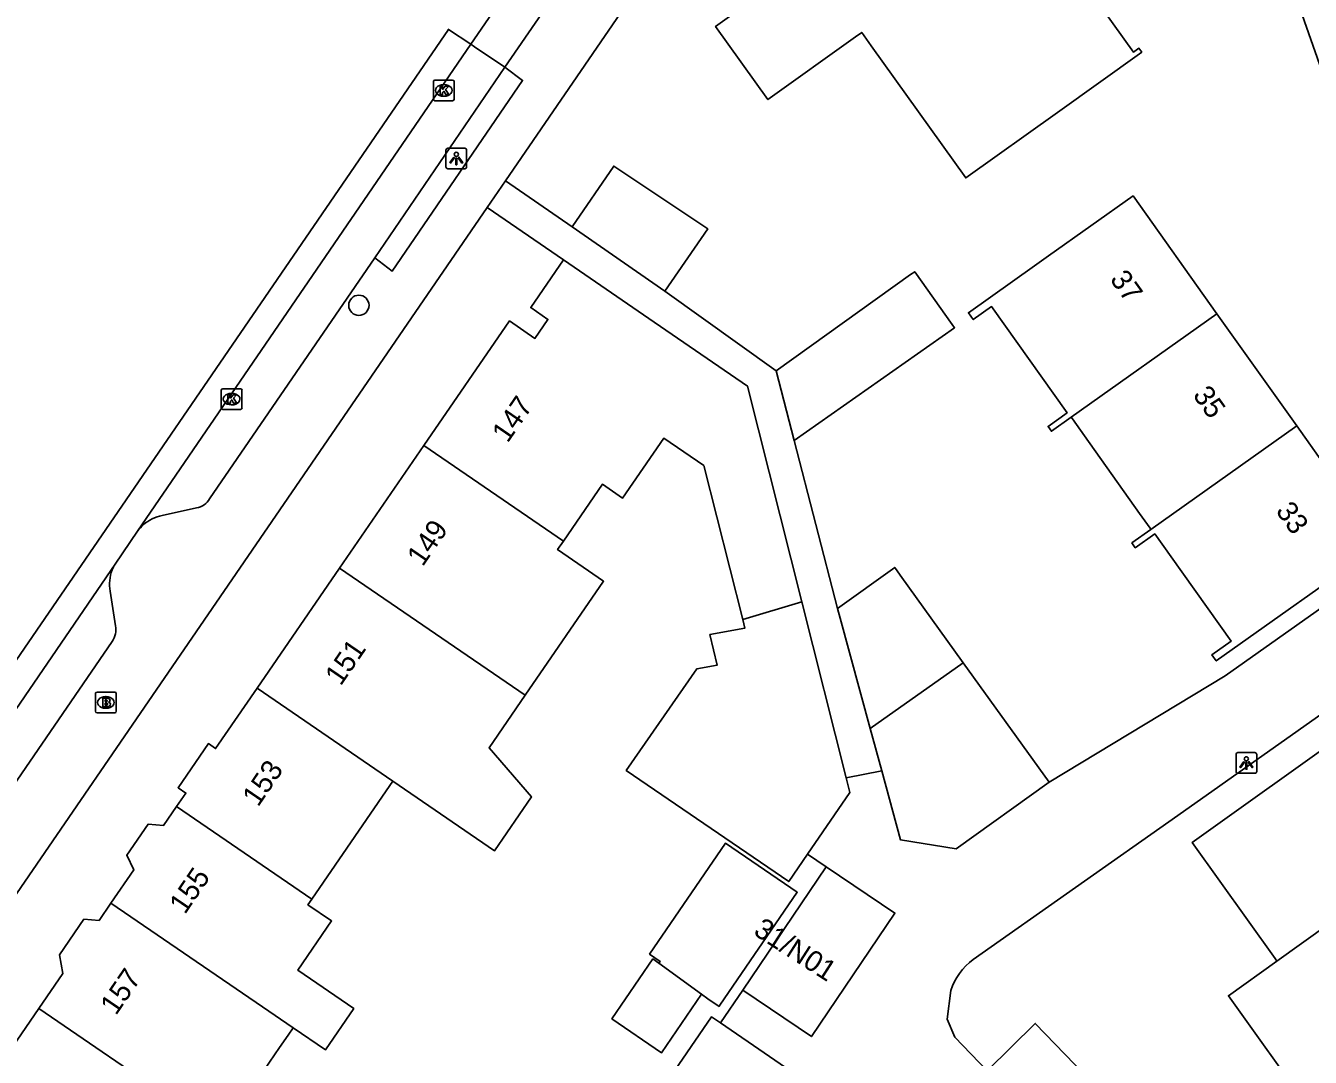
# Model space of a CAD drawing. Extents: x 160026 to 161302, y 384757 to 385701.
# Drawn here: x 160214.8 to 160276.8, y 385572.5 to 385622.3 of the extents above; entities that cross this region are included whole.
import ezdxf

# ---------------------------------------------------------------- set-up
doc = ezdxf.new("R2010")
doc.units = 0
for name, color, linetype in [('IMGEO_Boom', 7, 'Continuous'), ('IMGEO_Brandkraan', 7, 'Continuous'), ('IMGEO_Kolk', 7, 'Continuous'), ('IMGEO_Lichtpunt', 7, 'Continuous'), ('IMGEO_Muur', 7, 'Continuous'), ('IMGEO_Pand', 7, 'Continuous'), ('IMGEO_Pand_nummerreeks', 7, 'Continuous'), ('IMGEO_Parkeervlak_open', 7, 'Continuous'), ('IMGEO_Rijbaan_lokaal_gesloten', 7, 'Continuous'), ('IMGEO_Rijbaan_lokaal_open', 7, 'Continuous'), ('IMGEO_Voetpad_open', 7, 'Continuous')]:
    doc.layers.add(name, color=color, linetype=linetype)

msp = doc.modelspace()

# ---------------------------------------------------------------- linework, layer by layer
at = {"layer": 'IMGEO_Boom'}
msp.add_circle((160230.925, 385608.815), 0.489, dxfattribs=at)
at = {"layer": 'IMGEO_Brandkraan'}
for p, q in [((160218.217, 385589.217), (160218.217, 385590.069)), ((160218.292, 385590.143), (160219.144, 385590.143)), ((160219.218, 385590.069), (160219.218, 385589.217)), ((160218.728, 385589.363), (160218.703, 385589.363)), ((160218.705, 385589.923), (160218.73, 385589.923)), ((160219.144, 385589.143), (160218.292, 385589.143))]:
    msp.add_line(p, q, dxfattribs=at)
for points in [[(160218.217, 385589.217), (160218.217, 385590.069)], [(160218.292, 385590.143), (160219.144, 385590.143)], [(160219.218, 385590.069), (160219.218, 385589.217)], [(160218.565, 385589.843), (160218.565, 385589.443), (160218.778, 385589.443)], [(160218.796, 385589.843), (160218.565, 385589.843)], [(160218.744, 385589.762), (160218.69, 385589.762), (160218.69, 385589.686)], [(160218.69, 385589.686), (160218.743, 385589.686)], [(160218.752, 385589.61), (160218.69, 385589.61), (160218.69, 385589.529)], [(160218.69, 385589.529), (160218.752, 385589.529)], [(160219.144, 385589.143), (160218.292, 385589.143)]]:
    msp.add_lwpolyline(points, dxfattribs=at)
for centre, radius, start, end in [((160218.294, 385590.067), 0.0765, 91.55205, 178.44795), ((160218.294, 385590.067), 0.0765, 91.55205, 178.44795), ((160219.142, 385590.067), 0.0765, 1.55205, 88.44795), ((160219.142, 385590.067), 0.0765, 1.55205, 88.44795), ((160218.745, 385589.724), 0.0379, 267.82845, 90.93552), ((160218.753, 385589.569), 0.0404, 269.87594, 90.50774), ((160218.784, 385589.694), 0.251, 268.66757, 293.53466), ((160218.8, 385589.698), 0.145, 59.4692, 91.53667), ((160218.825, 385589.745), 0.0922, 285.51372, 58.15012), ((160218.83, 385589.553), 0.105, 301.31148, 78.98903), ((160218.294, 385589.219), 0.0765, 181.55205, 268.44795), ((160218.294, 385589.219), 0.0765, 181.55205, 268.44795), ((160219.142, 385589.219), 0.0765, 271.55205, 358.44795), ((160219.142, 385589.219), 0.0765, 271.55205, 358.44795)]:
    msp.add_arc(centre, radius, start, end, dxfattribs=at)
for centre, major_axis, ratio, start_param, end_param in [((160218.704, 385589.643), (-0.387, 0.002), 0.722429, 4.712389, 7.853982), ((160218.729, 385589.643), (-0.39, 0.002), 0.717154, 1.570796, 4.712389)]:
    msp.add_ellipse(centre, major_axis=major_axis, ratio=ratio, start_param=start_param, end_param=end_param, dxfattribs=at)
at = {"layer": 'IMGEO_Kolk'}
for p, q in [((160234.593, 385619.69), (160235.445, 385619.69)), ((160234.518, 385618.764), (160234.518, 385619.616)), ((160235.006, 385619.47), (160235.031, 385619.47)), ((160235.519, 385619.616), (160235.519, 385618.764)), ((160235.445, 385618.69), (160234.593, 385618.69)), ((160235.029, 385618.91), (160235.004, 385618.91)), ((160224.283, 385603.863), (160224.283, 385604.715)), ((160224.358, 385604.789), (160225.21, 385604.789)), ((160224.771, 385604.569), (160224.796, 385604.569)), ((160225.284, 385604.715), (160225.284, 385603.863)), ((160225.21, 385603.789), (160224.358, 385603.789)), ((160224.794, 385604.009), (160224.769, 385604.009))]:
    msp.add_line(p, q, dxfattribs=at)
for points in [[(160234.593, 385619.69), (160235.445, 385619.69)], [(160234.518, 385618.764), (160234.518, 385619.616)], [(160234.839, 385619.39), (160234.962, 385619.39), (160234.962, 385619.239), (160235.092, 385619.39), (160235.256, 385619.39), (160235.11, 385619.239), (160235.263, 385618.99), (160235.111, 385618.99), (160235.026, 385619.154), (160234.962, 385619.087), (160234.962, 385618.99), (160234.839, 385618.99), (160234.839, 385619.39)], [(160235.519, 385619.616), (160235.519, 385618.764)], [(160235.445, 385618.69), (160234.593, 385618.69)], [(160224.283, 385603.863), (160224.283, 385604.715)], [(160224.358, 385604.789), (160225.21, 385604.789)], [(160224.604, 385604.489), (160224.727, 385604.489), (160224.727, 385604.338), (160224.857, 385604.489), (160225.021, 385604.489), (160224.875, 385604.338), (160225.028, 385604.089), (160224.876, 385604.089), (160224.791, 385604.253), (160224.727, 385604.186), (160224.727, 385604.089), (160224.604, 385604.089), (160224.604, 385604.489)], [(160225.284, 385604.715), (160225.284, 385603.863)], [(160225.21, 385603.789), (160224.358, 385603.789)]]:
    msp.add_lwpolyline(points, dxfattribs=at)
for centre, start, end in [((160234.595, 385619.614), 91.55205, 178.44795), ((160234.595, 385619.614), 91.55205, 178.44795), ((160235.443, 385619.614), 1.55205, 88.44795), ((160235.443, 385619.614), 1.55205, 88.44795), ((160234.595, 385618.766), 181.55205, 268.44795), ((160234.595, 385618.766), 181.55205, 268.44795), ((160235.443, 385618.766), 271.55205, 358.44795), ((160235.443, 385618.766), 271.55205, 358.44795), ((160224.36, 385604.713), 91.55205, 178.44795), ((160224.36, 385604.713), 91.55205, 178.44795), ((160225.208, 385604.713), 1.55205, 88.44795), ((160225.208, 385604.713), 1.55205, 88.44795), ((160224.36, 385603.865), 181.55205, 268.44795), ((160224.36, 385603.865), 181.55205, 268.44795), ((160225.208, 385603.865), 271.55205, 358.44795), ((160225.208, 385603.865), 271.55205, 358.44795)]:
    msp.add_arc(centre, 0.0765, start, end, dxfattribs=at)
for centre, major_axis, ratio, start_param, end_param in [((160235.005, 385619.19), (-0.387, 0.002), 0.722429, 4.712389, 7.853982), ((160235.03, 385619.19), (-0.39, 0.002), 0.717154, 1.570796, 4.712389), ((160224.77, 385604.289), (-0.387, 0.002), 0.722429, 4.712389, 7.853982), ((160224.795, 385604.289), (-0.39, 0.002), 0.717154, 1.570796, 4.712389)]:
    msp.add_ellipse(centre, major_axis=major_axis, ratio=ratio, start_param=start_param, end_param=end_param, dxfattribs=at)
at = {"layer": 'IMGEO_Lichtpunt'}
for p, q in [((160235.125, 385616.307), (160235.125, 385615.5)), ((160235.125, 385616.307), (160235.125, 385615.5)), ((160236.027, 385616.402), (160235.219, 385616.402)), ((160236.027, 385616.402), (160235.219, 385616.402)), ((160236.121, 385615.5), (160236.121, 385616.307)), ((160236.121, 385615.5), (160236.121, 385616.307)), ((160235.219, 385615.406), (160236.027, 385615.406)), ((160235.219, 385615.406), (160236.027, 385615.406)), ((160273.242, 385587.125), (160273.242, 385586.318)), ((160273.242, 385587.125), (160273.242, 385586.318)), ((160274.144, 385587.22), (160273.336, 385587.22)), ((160274.144, 385587.22), (160273.336, 385587.22)), ((160274.238, 385586.318), (160274.238, 385587.125)), ((160274.238, 385586.318), (160274.238, 385587.125)), ((160273.336, 385586.224), (160274.144, 385586.224)), ((160273.336, 385586.224), (160274.144, 385586.224))]:
    msp.add_line(p, q, dxfattribs=at)
for points in [[(160235.499, 385615.971), (160235.538, 385615.943), (160235.35, 385615.681), (160235.312, 385615.708), (160235.499, 385615.971)], [(160235.711, 385615.943), (160235.749, 385615.97), (160235.936, 385615.708), (160235.897, 385615.68), (160235.711, 385615.943)], [(160235.601, 385615.923), (160235.648, 385615.923), (160235.648, 385615.601), (160235.601, 385615.601), (160235.601, 385615.923)], [(160273.616, 385586.789), (160273.655, 385586.761), (160273.467, 385586.499), (160273.429, 385586.526), (160273.616, 385586.789)], [(160273.718, 385586.741), (160273.765, 385586.741), (160273.765, 385586.419), (160273.718, 385586.419), (160273.718, 385586.741)], [(160273.828, 385586.761), (160273.866, 385586.788), (160274.053, 385586.526), (160274.014, 385586.498), (160273.828, 385586.761)]]:
    msp.add_lwpolyline(points, dxfattribs=at)
for centre in [(160235.624, 385616.105), (160273.741, 385586.923)]:
    msp.add_circle(centre, 0.0994, dxfattribs=at)
for centre, start, end in [((160235.219, 385616.307), 90, 180), ((160235.219, 385616.307), 90, 180), ((160236.027, 385616.307), 0, 90), ((160236.027, 385616.307), 0, 90), ((160235.219, 385615.5), 180, 270), ((160235.219, 385615.5), 180, 270), ((160236.027, 385615.5), 270, 0), ((160236.027, 385615.5), 270, 360), ((160273.336, 385587.125), 90, 180), ((160273.336, 385587.125), 90, 180), ((160274.144, 385587.125), 0, 90), ((160274.144, 385587.125), 0, 90), ((160273.336, 385586.318), 180, 270), ((160273.336, 385586.318), 180, 270), ((160274.144, 385586.318), 270, 0), ((160274.144, 385586.318), 270, 360)]:
    msp.add_arc(centre, 0.0946, start, end, dxfattribs=at)
at = {"layer": 'IMGEO_Muur'}
msp.add_lwpolyline([(160270.429, 385584.193), (160260.559, 385577.231)], dxfattribs=at)
msp.add_arc((160262.405, 385574.754), 3.089, 126.69414, 161.46561, dxfattribs=at)
at = {"layer": 'IMGEO_Pand'}
for points in [[(160255.639, 385621.348), (160255.181, 385621.987), (160254.879, 385621.771), (160250.657, 385618.751), (160248.134, 385622.277), (160261.677, 385631.967), (160261.827, 385631.757), (160261.029, 385631.186), (160268.291, 385621.038), (160268.557, 385621.228), (160268.691, 385621.041), (160264.625, 385618.131), (160260.204, 385614.967), (160255.639, 385621.348)], [(160241.217, 385612.605), (160243.222, 385615.534), (160247.754, 385612.501), (160245.685, 385609.496)], [(160272.318, 385608.412), (160268.274, 385614.099), (160264.199, 385611.202), (160263.523, 385610.721), (160260.333, 385608.453), (160260.565, 385608.127), (160261.446, 385608.754), (160265.093, 385603.626), (160264.171, 385602.97), (160264.334, 385602.74), (160265.285, 385603.415)], [(160245.685, 385609.496), (160241.217, 385612.605)], [(160234.057, 385602.042), (160238.191, 385608.061), (160239.414, 385607.221), (160240.043, 385608.136), (160239.212, 385608.707), (160240.794, 385611.01)], [(160240.794, 385611.01), (160244.916, 385608.18), (160249.668, 385604.916), (160252.292, 385594.495)], [(160251.057, 385605.648), (160257.541, 385610.298), (160257.738, 385610.439), (160259.549, 385607.896), (160259.663, 385607.736), (160251.93, 385602.297)], [(160265.285, 385603.415), (160272.318, 385608.412)], [(160276.172, 385602.992), (160272.318, 385608.412)], [(160251.93, 385602.297), (160251.057, 385605.648)], [(160265.285, 385603.415), (160265.344, 385603.332), (160265.923, 385602.518), (160268.588, 385598.77), (160269.094, 385598.058), (160269.138, 385597.996)], [(160269.138, 385597.996), (160268.217, 385597.342), (160268.382, 385597.11), (160269.32, 385597.777), (160270.104, 385596.675), (160273.001, 385592.6), (160272.079, 385591.944), (160272.289, 385591.649), (160280.273, 385597.325), (160279.748, 385598.064), (160280.15, 385598.35), (160278.334, 385600.905), (160277.884, 385600.585), (160276.172, 385602.992)], [(160276.172, 385602.992), (160269.138, 385597.996)], [(160249.444, 385593.645), (160247.561, 385601.076), (160245.63, 385602.401), (160243.644, 385599.509), (160242.675, 385600.174), (160240.79, 385597.43)], [(160229.996, 385596.128), (160234.057, 385602.042)], [(160234.057, 385602.042), (160240.79, 385597.43)], [(160240.79, 385597.43), (160240.511, 385597.023), (160242.732, 385595.498), (160238.951, 385589.992)], [(160226.016, 385590.334), (160229.996, 385596.128)], [(160238.951, 385589.992), (160229.996, 385596.128)], [(160260.079, 385591.562), (160257.039, 385595.795), (160256.775, 385596.163), (160254.017, 385594.181)], [(160252.292, 385594.495), (160249.444, 385593.645)], [(160254.428, 385586.011), (160252.292, 385594.495)], [(160252.572, 385582.317), (160251.666, 385580.993), (160243.821, 385586.361), (160247.222, 385591.264), (160248.213, 385591.449), (160247.856, 385592.921), (160249.548, 385593.236), (160249.444, 385593.645)], [(160254.017, 385594.181), (160254.144, 385593.715), (160255.598, 385588.379)], [(160255.598, 385588.379), (160260.079, 385591.562)], [(160260.079, 385591.562), (160264.225, 385585.791)], [(160222.125, 385584.613), (160222.577, 385585.271), (160222.202, 385585.529), (160223.664, 385587.657), (160224.013, 385587.417), (160226.016, 385590.334)], [(160232.567, 385585.846), (160226.016, 385590.334)], [(160238.951, 385589.992), (160237.208, 385587.454), (160239.251, 385585.081), (160237.47, 385582.487), (160232.567, 385585.846)], [(160256.151, 385586.349), (160255.598, 385588.379)], [(160282.799, 385582.585), (160282.699, 385582.725), (160282.154, 385582.335), (160278.37, 385587.629), (160278.919, 385588.022), (160278.716, 385588.306), (160271.123, 385582.879), (160275.126, 385577.279), (160275.212, 385577.159)], [(160264.225, 385585.791), (160259.743, 385582.571), (160257.06, 385583.011), (160256.151, 385586.349)], [(160232.567, 385585.846), (160232.422, 385585.634), (160228.652, 385580.146)], [(160254.428, 385586.011), (160254.609, 385585.293), (160252.572, 385582.317)], [(160218.96, 385579.954), (160220.061, 385581.558), (160219.724, 385582.264), (160220.754, 385583.763), (160221.501, 385583.705), (160222.125, 385584.613)], [(160222.125, 385584.613), (160228.652, 385580.146)], [(160247.459, 385575.557), (160247.762, 385575.337), (160248.299, 385574.969), (160248.345, 385575.037), (160252.071, 385580.482), (160248.61, 385582.85), (160244.944, 385577.493), (160245.456, 385577.143), (160245.397, 385577.056)], [(160282.799, 385582.585), (160275.212, 385577.159)], [(160253.469, 385581.711), (160256.782, 385579.474), (160252.757, 385573.513), (160249.444, 385575.749)], [(160249.444, 385575.749), (160253.469, 385581.711)], [(160228.652, 385580.146), (160228.468, 385579.878), (160229.603, 385579.099), (160227.971, 385576.723), (160230.678, 385574.864), (160229.306, 385572.867), (160227.751, 385573.932)], [(160215.484, 385574.871), (160216.647, 385576.564), (160216.479, 385577.465), (160217.658, 385579.182), (160218.39, 385579.124), (160218.96, 385579.954)], [(160227.751, 385573.932), (160226.268, 385574.948), (160218.96, 385579.954)], [(160245.397, 385577.056), (160245.108, 385577.266), (160243.128, 385574.373), (160245.527, 385572.731), (160247.459, 385575.557)], [(160247.459, 385575.557), (160245.397, 385577.056)], [(160275.212, 385577.159), (160272.874, 385575.487), (160276.793, 385570.004), (160279.143, 385571.646)], [(160211.989, 385569.803), (160212.375, 385570.365), (160212.067, 385571.011), (160213.079, 385572.486), (160213.806, 385572.429), (160215.484, 385574.871)], [(160215.484, 385574.871), (160222.245, 385570.239), (160222.783, 385569.871)], [(160245.767, 385571.299), (160247.943, 385574.468), (160248.377, 385574.17)], [(160227.751, 385573.932), (160227.508, 385573.578), (160227.098, 385572.981), (160226.132, 385571.574), (160227.844, 385570.398), (160226.299, 385568.149), (160223.104, 385570.338), (160222.783, 385569.871)], [(160248.377, 385574.17), (160253.349, 385570.755)], [(160261.237, 385571.865), (160263.552, 385574.147), (160269.287, 385568.199), (160266.942, 385565.957)]]:
    msp.add_lwpolyline(points, dxfattribs=at)
at = {"layer": 'IMGEO_Parkeervlak_open'}
for points in [[(160236.506, 385621.293), (160236.319, 385621.418)], [(160237.965, 385620.311), (160236.506, 385621.293)]]:
    msp.add_lwpolyline(points, dxfattribs=at)
at = {"layer": 'IMGEO_Rijbaan_lokaal_gesloten'}
for points in [[(160182.907, 385545.724), (160235.251, 385622.139)], [(160220.247, 385597.915), (160236.319, 385621.418)], [(160219.161, 385596.32), (160220.247, 385597.915)], [(160183.972, 385544.988), (160213.482, 385588.036), (160219.161, 385596.32)]]:
    msp.add_lwpolyline(points, dxfattribs=at)
at = {"layer": 'IMGEO_Rijbaan_lokaal_open'}
for points in [[(160236.319, 385621.418), (160241.364, 385628.754)], [(160235.251, 385622.139), (160235.223, 385622.158)], [(160235.251, 385622.139), (160236.319, 385621.418)], [(160284.678, 385599.386), (160272.709, 385590.922), (160264.225, 385585.791)], [(160286.104, 385595.25), (160270.429, 385584.193), (160260.559, 385577.231)], [(160256.151, 385586.349), (160254.428, 385586.011)], [(160252.572, 385582.317), (160253.469, 385581.711)], [(160249.444, 385575.749), (160248.377, 385574.17)], [(160259.476, 385575.736), (160259.306, 385574.361), (160259.678, 385573.485), (160261.237, 385571.865)]]:
    msp.add_lwpolyline(points, dxfattribs=at)
msp.add_arc((160262.405, 385574.754), 3.089, 126.69414, 161.46561, dxfattribs=at)
at = {"layer": 'IMGEO_Voetpad_open'}
for points in [[(160284.544, 385599.766), (160273.209, 385632.008), (160270.708, 385638.209), (160269.866, 385639.099), (160269.52, 385639.244)], [(160253.698, 385637.736), (160237.989, 385614.818)], [(160243.004, 385627.638), (160237.965, 385620.311)], [(160237.965, 385620.311), (160238.823, 385619.672), (160232.534, 385610.472), (160231.691, 385611.1)], [(160231.691, 385611.1), (160237.965, 385620.311)], [(160237.989, 385614.818), (160237.11, 385613.535)], [(160241.217, 385612.605), (160237.989, 385614.818)], [(160237.11, 385613.535), (160199.23, 385558.271)], [(160240.794, 385611.01), (160237.11, 385613.535)], [(160231.691, 385611.1), (160223.723, 385599.481)], [(160251.057, 385605.648), (160245.685, 385609.496)], [(160254.017, 385594.181), (160251.93, 385602.297)], [(160223.087, 385599.033), (160221.429, 385598.662)], [(160218.921, 385595.018), (160219.181, 385593.344)], [(160219.015, 385592.589), (160197.367, 385561)]]:
    msp.add_lwpolyline(points, dxfattribs=at)
for centre, radius, start, end in [((160222.957, 385599.893), 0.87, 278.59238, 331.72954), ((160221.802, 385596.759), 1.939, 101.08644, 130.75327), ((160221.858, 385596.717), 2.007, 131.19201, 143.37401), ((160220.763, 385595.354), 1.87, 148.90866, 158.45516), ((160220.778, 385595.349), 1.886, 158.49173, 190.12035), ((160218.236, 385593.156), 0.964, 323.95227, 11.24737)]:
    msp.add_arc(centre, radius, start, end, dxfattribs=at)

# ---------------------------------------------------------------- texts
at = {"layer": 'IMGEO_Pand_nummerreeks'}
for s, rotation, p in [('37', 305.57474, (160267.125, 385610.068)), ('35', 305.57474, (160271.125, 385604.477)), ('147', 55.51928, (160238.099, 385602.133)), ('33', 305.57474, (160275.125, 385598.885)), ('149', 55.51928, (160234.001, 385596.166)), ('151', 55.51961, (160230.046, 385590.406)), ('153', 55.77744, (160226.06, 385584.564)), ('155', 55.81182, (160222.531, 385579.375)), ('31/N01', 327.21572, (160249.907, 385578.469)), ('157', 55.6342, (160219.203, 385574.498))]:
    msp.add_text(s, height=1, rotation=rotation, dxfattribs=at).set_placement(p)

doc.saveas('drawing.dxf')
